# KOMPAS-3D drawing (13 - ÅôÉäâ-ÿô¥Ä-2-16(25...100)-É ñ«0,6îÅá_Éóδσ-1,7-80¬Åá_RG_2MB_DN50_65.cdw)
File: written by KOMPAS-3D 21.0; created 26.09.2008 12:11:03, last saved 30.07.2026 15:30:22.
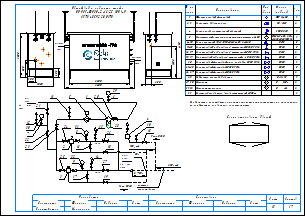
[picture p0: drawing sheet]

Sheets 1-2: A3, landscape

Document properties: Наименование: Макро:21; Автор: RaskoAdmin; Форматы листов документа: 2xA3; Полное имя файла: \\ur38nt01\Departments\КТО\КБ ПУРДГ\Заявки\Прайс-лист на типовые шкафы ГРПШ\ПУРДГ_стандарт_30_04_2026\ПУРДГ с RG_2MB\ПУРДГ-ШУЭО-2-16(25...100)-Р до0,6МПа_Рвых-1,7-80кПа_RG_2MB_DN50_65.cdw

Title block, sheet 1: Наименование: Пункт учета газа / ПУГ-Ш-400-Р / ЛГТИ.485922.001ТУ; designation: ЛГТИ.03.4411141; sheet number: 1; Количество листов документа: 2; organisation: ООО "ЭЛЬСТЕР Газэлектроника"; Форматы листов документа: A3; stored path: C:\Рабочие документы\Компас\ПУГ\Схема.cdw; Разработал: Устинов; Проверил: Кошкин; Утвердил: Кошкин
Title block, sheet 2: sheet number: 2; stored path: D:\Рабочие документы\Заявки\ПУРДГ\ПУРДГ-ШУЭО-2-100-Р 4411220.cdw; designation, second copy: ЛГТИ.03.4411141-

Views: Вид 1, Вид 2
Referenced files: wcvoit.frw
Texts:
  Normal
  № на
  схеме
  Усл.
  обозн.
  Марка
  (модель)
  Кол.
  Фильтр газовый фланцевый
  ФГ 16-50
  Регулятор давления газа
  RG/2MB
  Клапан предохранительный сбросной
  КПС DN20
  Измерительный комплекс с ротационным счетчиком Ду50
  СГ-ЭК-Р-(0,2...2,0)-
  Кран кнопочный VE-РАСКО-НЗ-1,6-G1/2-М20
  DN15
  Кран шаровой "под приварку" штуцерный DN20 PN16
  DN20
  Кран шаровой "под приварку" штуцерный DN15 PN16
  Кран шаровой "под приварку" штуцерный п/п DN20 PN16
  Кран шаровой фланцевый с мех. приводом DN50 PN16
  Кран шаровой фланцевый DN50 PN16
  Кран шаровой фланцевый DN65 PN16
  DN50
  DN65
  Индикатор перепада давления
  Манометр
  Манометр-напоромер
  Электрообогреватель взрывозащищенный 400Вт
  Delta 15
  0...     МПа
  0...     кПа
  Общий вид и габариты шкафа
  ПУРДГ-ШУЭО-2-16(25...100)-Р
  Выход газа
  Вход газа
  logo-rasko-ge.png
  DN 1
  местное
  сопротивление
  Римп DN20
  Выход
  газа
  Р=     кПа
  Вход
  Р=       МПа
  PDI
  Схема открывания дверей
  Предприятие изготовитель может заменять комплектующие на аналогичные,
  не ухудшающие заявленных характеристик.
  Должность
  Конструктор
  Фамилия
  Подпись
  Дата
  Согласовано
  Максимкин
  Лист
  Листов
  POLYLINE_STYLE_0.18_RGB_0_0_0
  POLYLINE_STYLE_0.50_RGB_0_0_0
  POLYLINE_STYLE_0.34_RGB_0_0_0
  PHANTOM_RGB_0_0_0_SC_1_THICK_0.18
  K5LT_THIN_RGB_0_0_0_THICK_0.18
  K5LT32769_RGB_0_0_0_THICK_0.18
  K5LT12_RGB_0_0_0_SC_1_THICK_0.18
  K5LT_DASHED_RGB_0_0_0_SC_1_THICK_0.18
  ACISOTGL_RGB_0_0_0_SC_0.8_THICK_0.25
  CONTINUOUS_RGB_0_127_31_THICK_0.3
  CONTINUOUS_RGB_0_0_255_THICK_0.35
  CONTINUOUS_RGB_255_0_0_THICK_0.35
  POLYLINE_STYLE_0.25_RGB_0_0_0
  CONTINUOUS_RGB_0_0_0_THICK_0.5
  POLYLINE_STYLE_0.35_RGB_0_0_255
  CONTINUOUS_RGB_0_0_0_THICK_0.4
  CONTINUOUS_RGB_0_0_0_THICK_0.35
  НЕВИДИМАЯ_RGB_0_0_0_SC_0.3_THICK_0.25
  СONTINUOUS_RGB_0_0_0_THICK_0.25
  ОСЕВАЯ2_RGB_248_153_30_SC_0.3_THICK_0.25
  Без оформления
Dimensions and other numbers on the sheet: 1; 2, 3; 2; 4; 5; 6-10; 11-15; 16, 17; 18, 19; 20; 21-25; 26, 27; 28; 29, 30; 31, 32; 33; 1500; 250; 300; 1050; 550; 305; 2300; 4130; 2000; 2600; 5,,,7DN 1; 7; 30; 12; 21; 22; 23; 11; 6; 29; 24; 31; 8; 16; 13; 26; 18; 10; 15; 25; 32; 9; 3; 17; 14; 27; 19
